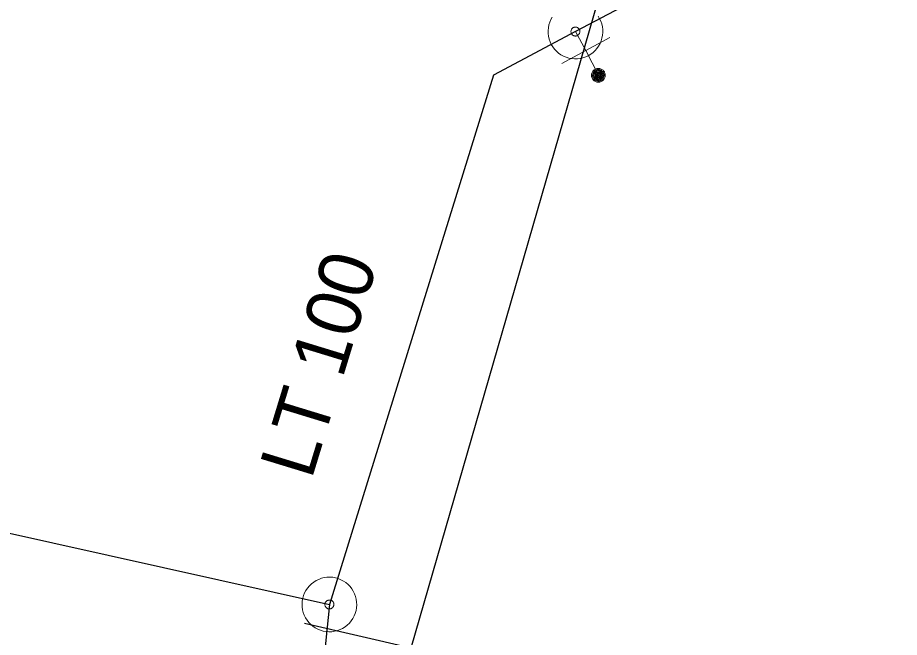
# Model space of a CAD drawing. Extents: x -774415 to -774100, y -975744 to -975502.
# Drawn here: x -774391.96 to -774375.83, y -975540.72 to -975529.39 of the extents above; entities that cross this region are included whole.
import ezdxf

# ---------------------------------------------------------------- set-up
doc = ezdxf.new("R2010")
doc.units = 0
doc.header["$LTSCALE"] = 0.4
doc.linetypes.add('MEDIUM_DASHED', pattern=[4.5, 3, -1.5])
for name, color, linetype, lineweight in [('1', 7, 'MEDIUM_DASHED', 25), ('14', 7, 'Continuous', 13), ('17', 7, 'Continuous', 25), ('34', 7, 'Continuous', 13), ('47', 7, 'Continuous', 13), ('9', 7, 'Continuous', 13)]:
    doc.layers.add(name, color=color, linetype=linetype, lineweight=lineweight)

msp = doc.modelspace()

# ---------------------------------------------------------------- linework, layer by layer
at = {"layer": '14'}
msp.add_lwpolyline([(-774381.76, -975529.64), (-774381.57, -975529.989), (-774381.34, -975530.44)], dxfattribs=at)
at = {"layer": '17'}
msp.add_line((-774399.638, -975537.139), (-774386.26, -975540.12), dxfattribs=at)
for points in [[(-774190.98, -975675.3), (-774195.739, -975661.53), (-774202.46, -975642.109), (-774207.43, -975626.379), (-774211.07, -975615.34), (-774217.71, -975595.969), (-774219.62, -975590.41), (-774224.989, -975576.25), (-774225.51, -975574.5), (-774226.62, -975573.949), (-774228.079, -975573.359), (-774258.14, -975564.129), (-774273.649, -975559.52), (-774289.02, -975554.649), (-774309.699, -975548.23), (-774320.17, -975544.98), (-774321.69, -975541.59), (-774344.199, -975534.469), (-774360.363, -975529.358), (-774373.359, -975525.199), (-774377.583, -975527.43), (-774378.039, -975527.68), (-774378.399, -975527.859), (-774381.76, -975529.64)], [(-774386.716, -975540.462), (-774384.765, -975540.912), (-774380.471, -975526.046), (-774380.382, -975525.739)], [(-774381.76, -975529.64), (-774383.26, -975530.44), (-774386.26, -975540.12)], [(-774386.26, -975540.12), (-774388.021, -975557.302), (-774388.021, -975557.726)]]:
    msp.add_lwpolyline(points, dxfattribs=at)
at = {"layer": '34'}
msp.add_line((-774381.13, -975529.75), (-774382.009, -975530.227), dxfattribs=at)
at = {"layer": '47'}
msp.add_lwpolyline([(-774382.184, -975529.375), (-774382.209, -975529.42), (-774382.229, -975529.468), (-774382.244, -975529.518), (-774382.254, -975529.57), (-774382.259, -975529.623), (-774382.258, -975529.675), (-774382.252, -975529.726), (-774382.24, -975529.778), (-774382.223, -975529.827), (-774382.201, -975529.875), (-774382.174, -975529.919), (-774382.142, -975529.961), (-774382.106, -975529.999), (-774382.067, -975530.034), (-774382.024, -975530.064), (-774381.978, -975530.089), (-774381.93, -975530.109), (-774381.88, -975530.124), (-774381.829, -975530.134), (-774381.776, -975530.139), (-774381.724, -975530.138), (-774381.672, -975530.131), (-774381.621, -975530.12), (-774381.572, -975530.103), (-774381.524, -975530.081), (-774381.48, -975530.054), (-774381.438, -975530.022), (-774381.399, -975529.986), (-774381.365, -975529.947), (-774381.335, -975529.904), (-774381.31, -975529.858), (-774381.289, -975529.809), (-774381.274, -975529.759), (-774381.264, -975529.708), (-774381.26, -975529.656), (-774381.261, -975529.604), (-774381.267, -975529.551), (-774381.279, -975529.501), (-774381.296, -975529.452), (-774381.318, -975529.404), (-774381.345, -975529.36)], dxfattribs=at)
for points in [[(-774381.832, -975529.678), (-774381.828, -975529.686), (-774381.822, -975529.692), (-774381.817, -975529.698), (-774381.81, -975529.704), (-774381.803, -975529.709), (-774381.795, -975529.713), (-774381.787, -975529.717), (-774381.779, -975529.719), (-774381.771, -975529.72), (-774381.762, -975529.721), (-774381.753, -975529.721), (-774381.745, -975529.72), (-774381.737, -975529.718), (-774381.729, -975529.716), (-774381.721, -975529.712), (-774381.713, -975529.708), (-774381.707, -975529.702), (-774381.701, -975529.697), (-774381.695, -975529.69), (-774381.69, -975529.683), (-774381.686, -975529.675), (-774381.682, -975529.667), (-774381.68, -975529.659), (-774381.678, -975529.65), (-774381.678, -975529.642), (-774381.678, -975529.633), (-774381.679, -975529.625), (-774381.681, -975529.617), (-774381.683, -975529.609), (-774381.687, -975529.601), (-774381.691, -975529.593), (-774381.697, -975529.587), (-774381.702, -975529.581), (-774381.709, -975529.575), (-774381.716, -975529.57), (-774381.723, -975529.566), (-774381.732, -975529.562), (-774381.74, -975529.56), (-774381.749, -975529.558), (-774381.757, -975529.558), (-774381.766, -975529.558), (-774381.774, -975529.559), (-774381.782, -975529.561), (-774381.79, -975529.563), (-774381.798, -975529.567), (-774381.806, -975529.571), (-774381.812, -975529.577), (-774381.818, -975529.582), (-774381.824, -975529.589), (-774381.829, -975529.596), (-774381.833, -975529.603), (-774381.837, -975529.612), (-774381.839, -975529.62), (-774381.84, -975529.628), (-774381.841, -975529.637), (-774381.841, -975529.646), (-774381.84, -975529.654), (-774381.838, -975529.662), (-774381.836, -975529.67)], [(-774385.772, -975540.232), (-774385.763, -975540.18), (-774385.76, -975540.128), (-774385.762, -975540.076), (-774385.769, -975540.024), (-774385.781, -975539.973), (-774385.8, -975539.924), (-774385.823, -975539.877), (-774385.851, -975539.833), (-774385.882, -975539.792), (-774385.919, -975539.754), (-774385.959, -975539.72), (-774386.003, -975539.691), (-774386.049, -975539.666), (-774386.097, -975539.647), (-774386.147, -975539.632), (-774386.199, -975539.623), (-774386.251, -975539.62), (-774386.304, -975539.622), (-774386.355, -975539.629), (-774386.406, -975539.641), (-774386.455, -975539.66), (-774386.503, -975539.683), (-774386.547, -975539.711), (-774386.588, -975539.742), (-774386.625, -975539.779), (-774386.659, -975539.819), (-774386.689, -975539.863), (-774386.713, -975539.909), (-774386.732, -975539.957), (-774386.747, -975540.007), (-774386.756, -975540.059), (-774386.759, -975540.111), (-774386.758, -975540.164), (-774386.75, -975540.215), (-774386.738, -975540.266), (-774386.72, -975540.315), (-774386.697, -975540.363), (-774386.669, -975540.407), (-774386.637, -975540.448), (-774386.6, -975540.485), (-774386.56, -975540.519), (-774386.517, -975540.549), (-774386.47, -975540.573), (-774386.422, -975540.592), (-774386.372, -975540.607), (-774386.32, -975540.616), (-774386.268, -975540.619), (-774386.216, -975540.618), (-774386.164, -975540.61), (-774386.113, -975540.598), (-774386.064, -975540.58), (-774386.017, -975540.557), (-774385.973, -975540.529), (-774385.932, -975540.497), (-774385.894, -975540.46), (-774385.86, -975540.42), (-774385.831, -975540.377), (-774385.806, -975540.33), (-774385.787, -975540.282)], [(-774386.18, -975540.138), (-774386.178, -975540.129), (-774386.178, -975540.121), (-774386.178, -975540.113), (-774386.179, -975540.104), (-774386.181, -975540.095), (-774386.184, -975540.088), (-774386.188, -975540.08), (-774386.192, -975540.072), (-774386.198, -975540.066), (-774386.204, -975540.059), (-774386.211, -975540.054), (-774386.218, -975540.049), (-774386.225, -975540.045), (-774386.232, -975540.042), (-774386.241, -975540.04), (-774386.25, -975540.038), (-774386.258, -975540.038), (-774386.266, -975540.038), (-774386.275, -975540.039), (-774386.284, -975540.041), (-774386.291, -975540.044), (-774386.299, -975540.048), (-774386.307, -975540.052), (-774386.314, -975540.058), (-774386.32, -975540.064), (-774386.325, -975540.071), (-774386.33, -975540.078), (-774386.334, -975540.085), (-774386.337, -975540.092), (-774386.339, -975540.101), (-774386.341, -975540.11), (-774386.341, -975540.118), (-774386.341, -975540.126), (-774386.34, -975540.135), (-774386.338, -975540.144), (-774386.336, -975540.151), (-774386.331, -975540.159), (-774386.327, -975540.167), (-774386.321, -975540.174), (-774386.315, -975540.18), (-774386.308, -975540.185), (-774386.301, -975540.19), (-774386.294, -975540.194), (-774386.287, -975540.197), (-774386.278, -975540.199), (-774386.269, -975540.201), (-774386.261, -975540.201), (-774386.253, -975540.201), (-774386.244, -975540.2), (-774386.235, -975540.198), (-774386.228, -975540.196), (-774386.22, -975540.191), (-774386.212, -975540.187), (-774386.206, -975540.181), (-774386.199, -975540.175), (-774386.194, -975540.168), (-774386.189, -975540.161), (-774386.185, -975540.154), (-774386.182, -975540.147)]]:
    msp.add_lwpolyline(points, close=True, dxfattribs=at)
at = {"layer": '9'}
for points in [[(-774381.466, -975530.44), (-774381.466, -975530.453), (-774381.463, -975530.466), (-774381.461, -975530.479), (-774381.456, -975530.491), (-774381.45, -975530.503), (-774381.443, -975530.514), (-774381.434, -975530.524), (-774381.424, -975530.534), (-774381.414, -975530.542), (-774381.404, -975530.549), (-774381.392, -975530.555), (-774381.38, -975530.56), (-774381.367, -975530.563), (-774381.353, -975530.565), (-774381.341, -975530.567), (-774381.328, -975530.566), (-774381.315, -975530.564), (-774381.302, -975530.561), (-774381.289, -975530.556), (-774381.277, -975530.55), (-774381.267, -975530.543), (-774381.257, -975530.535), (-774381.247, -975530.525), (-774381.239, -975530.515), (-774381.232, -975530.504), (-774381.226, -975530.492), (-774381.221, -975530.48), (-774381.218, -975530.467), (-774381.216, -975530.454), (-774381.213, -975530.441), (-774381.215, -975530.428), (-774381.217, -975530.415), (-774381.22, -975530.402), (-774381.225, -975530.39), (-774381.23, -975530.378), (-774381.238, -975530.367), (-774381.245, -975530.357), (-774381.255, -975530.347), (-774381.266, -975530.339), (-774381.277, -975530.332), (-774381.289, -975530.326), (-774381.301, -975530.321), (-774381.314, -975530.318), (-774381.326, -975530.316), (-774381.34, -975530.315), (-774381.353, -975530.315), (-774381.365, -975530.317), (-774381.379, -975530.32), (-774381.391, -975530.325), (-774381.402, -975530.331), (-774381.414, -975530.338), (-774381.424, -975530.346), (-774381.434, -975530.356), (-774381.441, -975530.366), (-774381.449, -975530.377), (-774381.455, -975530.389), (-774381.46, -975530.401), (-774381.463, -975530.414), (-774381.465, -975530.427)], [(-774381.446, -975530.44), (-774381.446, -975530.451), (-774381.445, -975530.462), (-774381.441, -975530.473), (-774381.438, -975530.483), (-774381.433, -975530.493), (-774381.427, -975530.502), (-774381.419, -975530.511), (-774381.412, -975530.519), (-774381.402, -975530.526), (-774381.394, -975530.532), (-774381.384, -975530.537), (-774381.374, -975530.541), (-774381.363, -975530.544), (-774381.352, -975530.547), (-774381.341, -975530.547), (-774381.33, -975530.547), (-774381.319, -975530.545), (-774381.308, -975530.542), (-774381.298, -975530.538), (-774381.288, -975530.533), (-774381.279, -975530.527), (-774381.27, -975530.52), (-774381.262, -975530.512), (-774381.255, -975530.503), (-774381.249, -975530.494), (-774381.244, -975530.484), (-774381.24, -975530.474), (-774381.237, -975530.463), (-774381.235, -975530.452), (-774381.233, -975530.441), (-774381.233, -975530.43), (-774381.235, -975530.419), (-774381.239, -975530.408), (-774381.243, -975530.398), (-774381.248, -975530.388), (-774381.254, -975530.379), (-774381.261, -975530.37), (-774381.269, -975530.362), (-774381.277, -975530.355), (-774381.287, -975530.349), (-774381.297, -975530.344), (-774381.306, -975530.34), (-774381.318, -975530.337), (-774381.328, -975530.335), (-774381.34, -975530.335), (-774381.351, -975530.334), (-774381.362, -975530.336), (-774381.373, -975530.339), (-774381.382, -975530.343), (-774381.392, -975530.348), (-774381.402, -975530.354), (-774381.411, -975530.361), (-774381.419, -975530.369), (-774381.426, -975530.378), (-774381.431, -975530.387), (-774381.436, -975530.397), (-774381.441, -975530.407), (-774381.444, -975530.418), (-774381.446, -975530.429)], [(-774381.427, -975530.44), (-774381.427, -975530.449), (-774381.426, -975530.458), (-774381.423, -975530.467), (-774381.419, -975530.475), (-774381.416, -975530.483), (-774381.411, -975530.491), (-774381.404, -975530.498), (-774381.399, -975530.504), (-774381.392, -975530.51), (-774381.384, -975530.515), (-774381.375, -975530.519), (-774381.368, -975530.522), (-774381.358, -975530.525), (-774381.35, -975530.526), (-774381.341, -975530.528), (-774381.331, -975530.527), (-774381.323, -975530.526), (-774381.314, -975530.523), (-774381.306, -975530.52), (-774381.298, -975530.516), (-774381.289, -975530.511), (-774381.282, -975530.505), (-774381.277, -975530.499), (-774381.271, -975530.492), (-774381.266, -975530.484), (-774381.262, -975530.476), (-774381.259, -975530.468), (-774381.255, -975530.459), (-774381.255, -975530.45), (-774381.252, -975530.441), (-774381.254, -975530.432), (-774381.255, -975530.423), (-774381.257, -975530.414), (-774381.261, -975530.406), (-774381.265, -975530.398), (-774381.27, -975530.39), (-774381.276, -975530.383), (-774381.282, -975530.377), (-774381.289, -975530.371), (-774381.297, -975530.366), (-774381.304, -975530.362), (-774381.313, -975530.359), (-774381.321, -975530.356), (-774381.331, -975530.355), (-774381.34, -975530.354), (-774381.348, -975530.354), (-774381.358, -975530.355), (-774381.367, -975530.358), (-774381.375, -975530.361), (-774381.382, -975530.365), (-774381.391, -975530.37), (-774381.397, -975530.376), (-774381.404, -975530.382), (-774381.409, -975530.389), (-774381.414, -975530.397), (-774381.419, -975530.405), (-774381.422, -975530.413), (-774381.424, -975530.422), (-774381.426, -975530.431)], [(-774381.407, -975530.44), (-774381.407, -975530.447), (-774381.406, -975530.454), (-774381.404, -975530.461), (-774381.402, -975530.467), (-774381.399, -975530.473), (-774381.395, -975530.479), (-774381.391, -975530.485), (-774381.386, -975530.49), (-774381.38, -975530.494), (-774381.374, -975530.498), (-774381.368, -975530.501), (-774381.362, -975530.504), (-774381.355, -975530.505), (-774381.348, -975530.508), (-774381.341, -975530.508), (-774381.333, -975530.508), (-774381.326, -975530.506), (-774381.32, -975530.505), (-774381.314, -975530.502), (-774381.306, -975530.499), (-774381.302, -975530.495), (-774381.296, -975530.491), (-774381.291, -975530.486), (-774381.287, -975530.48), (-774381.282, -975530.474), (-774381.279, -975530.468), (-774381.277, -975530.462), (-774381.275, -975530.455), (-774381.274, -975530.448), (-774381.272, -975530.441), (-774381.272, -975530.434), (-774381.274, -975530.427), (-774381.276, -975530.42), (-774381.279, -975530.414), (-774381.282, -975530.407), (-774381.286, -975530.402), (-774381.289, -975530.396), (-774381.294, -975530.391), (-774381.301, -975530.387), (-774381.306, -975530.383), (-774381.313, -975530.38), (-774381.319, -975530.377), (-774381.326, -975530.375), (-774381.333, -975530.374), (-774381.34, -975530.374), (-774381.347, -975530.374), (-774381.353, -975530.374), (-774381.36, -975530.376), (-774381.367, -975530.379), (-774381.373, -975530.382), (-774381.379, -975530.386), (-774381.385, -975530.39), (-774381.39, -975530.395), (-774381.394, -975530.401), (-774381.397, -975530.406), (-774381.401, -975530.413), (-774381.404, -975530.419), (-774381.404, -975530.426), (-774381.407, -975530.433)], [(-774381.387, -975530.44), (-774381.387, -975530.445), (-774381.387, -975530.45), (-774381.386, -975530.455), (-774381.384, -975530.459), (-774381.382, -975530.464), (-774381.379, -975530.468), (-774381.375, -975530.471), (-774381.372, -975530.475), (-774381.369, -975530.478), (-774381.365, -975530.481), (-774381.36, -975530.483), (-774381.355, -975530.485), (-774381.351, -975530.486), (-774381.346, -975530.488), (-774381.341, -975530.488), (-774381.336, -975530.488), (-774381.331, -975530.487), (-774381.326, -975530.486), (-774381.321, -975530.484), (-774381.316, -975530.482), (-774381.313, -975530.479), (-774381.309, -975530.476), (-774381.306, -975530.472), (-774381.303, -975530.469), (-774381.299, -975530.465), (-774381.298, -975530.46), (-774381.296, -975530.456), (-774381.294, -975530.451), (-774381.294, -975530.446), (-774381.293, -975530.441), (-774381.293, -975530.436), (-774381.294, -975530.431), (-774381.294, -975530.426), (-774381.297, -975530.422), (-774381.299, -975530.417), (-774381.302, -975530.413), (-774381.304, -975530.409), (-774381.308, -975530.406), (-774381.311, -975530.403), (-774381.316, -975530.4), (-774381.321, -975530.398), (-774381.325, -975530.396), (-774381.33, -975530.395), (-774381.335, -975530.394), (-774381.34, -975530.394), (-774381.345, -975530.394), (-774381.35, -975530.395), (-774381.355, -975530.395), (-774381.358, -975530.397), (-774381.364, -975530.399), (-774381.368, -975530.402), (-774381.37, -975530.405), (-774381.375, -975530.408), (-774381.377, -975530.412), (-774381.38, -975530.416), (-774381.382, -975530.421), (-774381.385, -975530.425), (-774381.386, -975530.43), (-774381.387, -975530.435)], [(-774381.367, -975530.44), (-774381.367, -975530.443), (-774381.368, -975530.446), (-774381.367, -975530.448), (-774381.365, -975530.451), (-774381.365, -975530.454), (-774381.363, -975530.456), (-774381.36, -975530.458), (-774381.358, -975530.46), (-774381.357, -975530.462), (-774381.355, -975530.464), (-774381.352, -975530.466), (-774381.348, -975530.467), (-774381.347, -975530.467), (-774381.343, -975530.468), (-774381.341, -975530.468), (-774381.338, -975530.468), (-774381.335, -975530.468), (-774381.331, -975530.467), (-774381.33, -975530.466), (-774381.326, -975530.465), (-774381.325, -975530.463), (-774381.321, -975530.461), (-774381.32, -975530.459), (-774381.319, -975530.457), (-774381.316, -975530.455), (-774381.316, -975530.452), (-774381.314, -975530.449), (-774381.314, -975530.447), (-774381.313, -975530.444), (-774381.311, -975530.441), (-774381.313, -975530.438), (-774381.313, -975530.435), (-774381.314, -975530.432), (-774381.315, -975530.43), (-774381.316, -975530.427), (-774381.318, -975530.425), (-774381.319, -975530.422), (-774381.321, -975530.42), (-774381.324, -975530.419), (-774381.326, -975530.417), (-774381.328, -975530.416), (-774381.331, -975530.415), (-774381.333, -975530.414), (-774381.337, -975530.414), (-774381.34, -975530.413), (-774381.343, -975530.414), (-774381.346, -975530.413), (-774381.348, -975530.415), (-774381.351, -975530.415), (-774381.353, -975530.416), (-774381.355, -975530.418), (-774381.358, -975530.419), (-774381.36, -975530.421), (-774381.362, -975530.424), (-774381.364, -975530.426), (-774381.365, -975530.429), (-774381.365, -975530.431), (-774381.367, -975530.434), (-774381.367, -975530.437)], [(-774381.348, -975530.44), (-774381.348, -975530.442), (-774381.348, -975530.442), (-774381.347, -975530.442), (-774381.347, -975530.444), (-774381.348, -975530.445), (-774381.346, -975530.445), (-774381.346, -975530.445), (-774381.346, -975530.447), (-774381.346, -975530.447), (-774381.345, -975530.448), (-774381.343, -975530.448), (-774381.343, -975530.448), (-774381.343, -975530.449), (-774381.341, -975530.449), (-774381.341, -975530.449), (-774381.34, -975530.449), (-774381.338, -975530.449), (-774381.338, -975530.448), (-774381.338, -975530.448), (-774381.336, -975530.448), (-774381.336, -975530.447), (-774381.336, -975530.447), (-774381.335, -975530.446), (-774381.335, -975530.446), (-774381.333, -975530.445), (-774381.333, -975530.444), (-774381.331, -975530.443), (-774381.331, -975530.443), (-774381.331, -975530.442), (-774381.331, -975530.441), (-774381.331, -975530.44), (-774381.331, -975530.439), (-774381.331, -975530.439), (-774381.333, -975530.438), (-774381.333, -975530.437), (-774381.333, -975530.436), (-774381.333, -975530.436), (-774381.335, -975530.435), (-774381.335, -975530.435), (-774381.336, -975530.434), (-774381.337, -975530.434), (-774381.338, -975530.433), (-774381.338, -975530.433), (-774381.338, -975530.433), (-774381.34, -975530.433), (-774381.341, -975530.433), (-774381.342, -975530.433), (-774381.342, -975530.433), (-774381.343, -975530.434), (-774381.343, -975530.433), (-774381.345, -975530.435), (-774381.345, -975530.435), (-774381.346, -975530.435), (-774381.346, -975530.435), (-774381.347, -975530.437), (-774381.347, -975530.438), (-774381.347, -975530.439), (-774381.348, -975530.439), (-774381.348, -975530.44)]]:
    msp.add_lwpolyline(points, close=True, dxfattribs=at)

# ---------------------------------------------------------------- texts
at = {"layer": '1'}
msp.add_text('LT 100', height=1, rotation=73, dxfattribs=at).set_placement((-774386.588, -975537.853))

doc.saveas('drawing.dxf')
